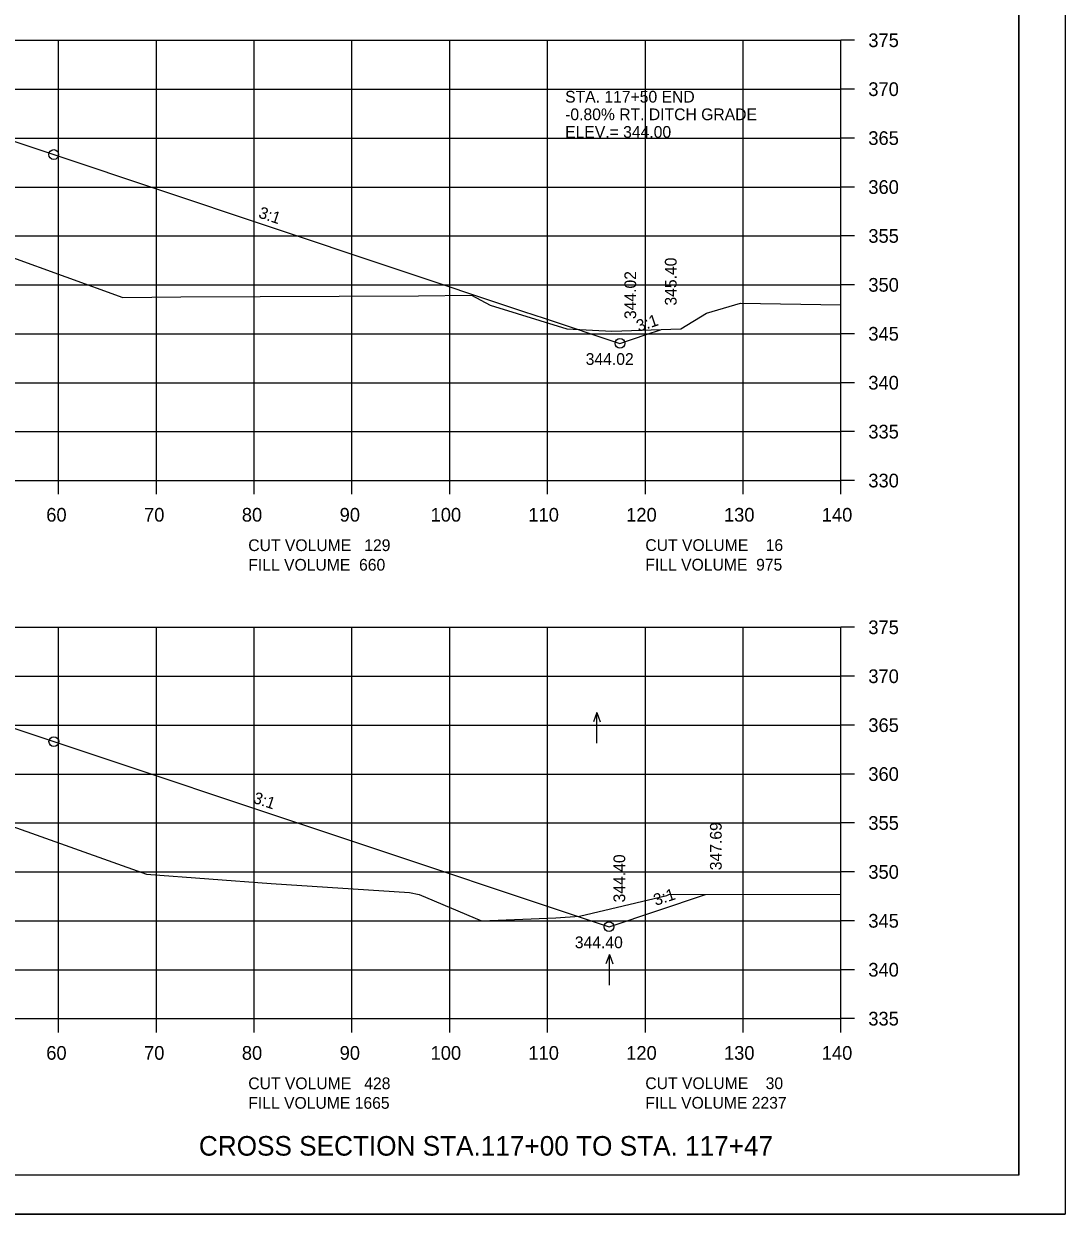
# Model space of a CAD drawing. Extents: x 1374859 to 1376773, y 382242 to 389804.
# Drawn here: x 1376191 to 1376297.5, y 383521.8 to 383643.4 of the extents above; entities that cross this region are included whole.
import ezdxf

# ---------------------------------------------------------------- set-up
doc = ezdxf.new("R2010")
doc.units = 0
for name, color, linetype in [('R_Axis', 7, 'Continuous'), ('R_Axis Annot', 7, 'Continuous'), ('R_Border', 7, 'Continuous'), ('R_Detour Annot', 7, 'Continuous'), ('R_Draft', 7, 'Continuous'), ('R_Exist Surface', 7, 'Continuous'), ('R_Fin Surface', 7, 'Continuous'), ('R_Grid', 7, 'Continuous'), ('R_No Plot', 7, 'Continuous'), ('R_Water Annot', 7, 'Continuous'), ('R_Xsect Elev', 7, 'Continuous'), ('R_Xsect Slope', 7, 'Continuous')]:
    doc.layers.add(name, color=color, linetype=linetype)

msp = doc.modelspace()

# ---------------------------------------------------------------- linework, layer by layer
at = {"layer": 'R_Axis'}
for p, q in [((1376274.57, 383596.75), (1376274.57, 383641.75)), ((1376275.97, 383641.75), (1376274.57, 383641.75)), ((1376275.97, 383636.75), (1376274.57, 383636.75)), ((1376275.97, 383631.75), (1376274.57, 383631.75)), ((1376275.97, 383626.75), (1376274.57, 383626.75)), ((1376275.97, 383621.75), (1376274.57, 383621.75)), ((1376275.97, 383616.75), (1376274.57, 383616.75)), ((1376275.97, 383611.75), (1376274.57, 383611.75)), ((1376275.97, 383606.75), (1376274.57, 383606.75)), ((1376275.97, 383601.75), (1376274.57, 383601.75)), ((1375994.57, 383596.75), (1376274.57, 383596.75)), ((1376194.57, 383595.35), (1376194.57, 383596.75)), ((1376204.57, 383595.35), (1376204.57, 383596.75)), ((1376214.57, 383595.35), (1376214.57, 383596.75)), ((1376224.57, 383595.35), (1376224.57, 383596.75)), ((1376234.57, 383595.35), (1376234.57, 383596.75)), ((1376244.57, 383595.35), (1376244.57, 383596.75)), ((1376254.57, 383595.35), (1376254.57, 383596.75)), ((1376264.57, 383595.35), (1376264.57, 383596.75)), ((1376274.57, 383595.35), (1376274.57, 383596.75)), ((1376275.97, 383596.75), (1376274.57, 383596.75)), ((1376274.57, 383541.75), (1376274.57, 383581.75)), ((1376275.97, 383581.75), (1376274.57, 383581.75)), ((1376275.97, 383576.75), (1376274.57, 383576.75)), ((1376275.97, 383571.75), (1376274.57, 383571.75)), ((1376275.97, 383566.75), (1376274.57, 383566.75)), ((1376275.97, 383561.75), (1376274.57, 383561.75)), ((1376275.97, 383556.75), (1376274.57, 383556.75)), ((1376275.97, 383551.75), (1376274.57, 383551.75)), ((1376275.97, 383546.75), (1376274.57, 383546.75)), ((1375994.57, 383541.75), (1376274.57, 383541.75)), ((1376194.57, 383540.35), (1376194.57, 383541.75)), ((1376204.57, 383540.35), (1376204.57, 383541.75)), ((1376214.57, 383540.35), (1376214.57, 383541.75)), ((1376224.57, 383540.35), (1376224.57, 383541.75)), ((1376234.57, 383540.35), (1376234.57, 383541.75)), ((1376244.57, 383540.35), (1376244.57, 383541.75)), ((1376254.57, 383540.35), (1376254.57, 383541.75)), ((1376264.57, 383540.35), (1376264.57, 383541.75)), ((1376274.57, 383540.35), (1376274.57, 383541.75)), ((1376275.97, 383541.75), (1376274.57, 383541.75))]:
    msp.add_line(p, q, dxfattribs=at)
at = {"layer": 'R_Border'}
for q in [(1376292.75, 383731.21), (1375976.57, 383525.75)]:
    msp.add_line((1376292.75, 383525.75), q, dxfattribs=at)
at = {"layer": 'R_Exist Surface'}
for points in [[(1376177.8, 383623.92), (1376201.15, 383615.47), (1376207.06, 383615.53), (1376231.38, 383615.64), (1376236.8, 383615.7), (1376238.7, 383614.67), (1376246.54, 383612.27), (1376251.16, 383612.03), (1376258.19, 383612.24), (1376260.84, 383613.84), (1376264.29, 383614.89), (1376274.57, 383614.72)], [(1376182.38, 383564.04), (1376203.57, 383556.51), (1376216.32, 383555.58), (1376230.46, 383554.66), (1376231.44, 383554.43), (1376237.83, 383551.76), (1376245.42, 383552.07), (1376247.84, 383552.23), (1376256.76, 383554.35), (1376256.98, 383554.43), (1376274.57, 383554.49)]]:
    msp.add_lwpolyline(points, dxfattribs=at)
at = {"layer": 'R_Fin Surface'}
for points in [[(1376021.3, 383605.53), (1376091.7, 383628.96), (1376098.93, 383629.52), (1376105.08, 383629.99), (1376127.64, 383631.73), (1376134.58, 383632.26), (1376157.14, 383634), (1376164.08, 383634.53), (1376167.2, 383634.77), (1376177.58, 383635.57), (1376183.84, 383633.48), (1376185.75, 383632.85), (1376192.14, 383630.72), (1376194.08, 383630.07), (1376215.8, 383622.83), (1376242.12, 383614.04), (1376244.24, 383613.34), (1376251.97, 383610.77), (1376254.66, 383611.67), (1376256.11, 383612.15)], [(1376005.04, 383556.78), (1376025.94, 383549.82), (1376075.09, 383566.2), (1376077.63, 383566.62), (1376091.59, 383568.95), (1376105.09, 383569.99), (1376134.59, 383572.26), (1376164.09, 383574.53), (1376177.59, 383575.57), (1376185.76, 383572.85), (1376194.09, 383570.07), (1376250.86, 383551.15), (1376260.73, 383554.44)]]:
    msp.add_lwpolyline(points, dxfattribs=at)
at = {"layer": 'R_Grid'}
for p, q in [((1375994.57, 383641.75), (1376274.57, 383641.75)), ((1376194.57, 383596.75), (1376194.57, 383641.75)), ((1376204.57, 383596.75), (1376204.57, 383641.75)), ((1376214.57, 383596.75), (1376214.57, 383641.75)), ((1376224.57, 383596.75), (1376224.57, 383641.75)), ((1376234.57, 383596.75), (1376234.57, 383641.75)), ((1376244.57, 383596.75), (1376244.57, 383641.75)), ((1376254.57, 383596.75), (1376254.57, 383641.75)), ((1376264.57, 383596.75), (1376264.57, 383641.75)), ((1376274.57, 383596.75), (1376274.57, 383641.75)), ((1375994.57, 383636.75), (1376274.57, 383636.75)), ((1375994.57, 383631.75), (1376274.57, 383631.75)), ((1375994.57, 383626.75), (1376274.57, 383626.75)), ((1375994.57, 383621.75), (1376274.57, 383621.75)), ((1375994.57, 383616.75), (1376274.57, 383616.75)), ((1375994.57, 383611.75), (1376274.57, 383611.75)), ((1375994.57, 383606.75), (1376274.57, 383606.75)), ((1375994.57, 383601.75), (1376274.57, 383601.75)), ((1375994.57, 383596.75), (1376274.57, 383596.75)), ((1375994.57, 383581.75), (1376274.57, 383581.75)), ((1376194.57, 383541.75), (1376194.57, 383581.75)), ((1376204.57, 383541.75), (1376204.57, 383581.75)), ((1376214.57, 383541.75), (1376214.57, 383581.75)), ((1376224.57, 383541.75), (1376224.57, 383581.75)), ((1376234.57, 383541.75), (1376234.57, 383581.75)), ((1376244.57, 383541.75), (1376244.57, 383581.75)), ((1376254.57, 383541.75), (1376254.57, 383581.75)), ((1376264.57, 383541.75), (1376264.57, 383581.75)), ((1376274.57, 383541.75), (1376274.57, 383581.75)), ((1375994.57, 383576.75), (1376274.57, 383576.75)), ((1375994.57, 383571.75), (1376274.57, 383571.75)), ((1375994.57, 383566.75), (1376274.57, 383566.75)), ((1375994.57, 383561.75), (1376274.57, 383561.75)), ((1375994.57, 383556.75), (1376274.57, 383556.75)), ((1375994.57, 383551.75), (1376274.57, 383551.75)), ((1375994.57, 383546.75), (1376274.57, 383546.75)), ((1375994.57, 383541.75), (1376274.57, 383541.75))]:
    msp.add_line(p, q, dxfattribs=at)
at = {"layer": 'R_No Plot'}
msp.add_line((1375964.17, 383521.77), (1376297.5, 383521.77), dxfattribs=at)
for points in [[(1375964.16, 383735.1), (1376297.5, 383735.1), (1376297.5, 383521.77), (1375964.16, 383521.77)], [(1376210.49, 383731.21), (1376210.49, 383721.33), (1376246.22, 383721.33), (1376246.22, 383718.41), (1376269.42, 383718.41), (1376269.42, 383694.08), (1376292.75, 383694.08), (1376292.75, 383525.75), (1375976.57, 383525.75), (1375976.57, 383731.21)]]:
    msp.add_lwpolyline(points, close=True, dxfattribs=at)
for centre in [(1376194.08, 383630.07), (1376251.97, 383610.77), (1376194.09, 383570.07), (1376250.86, 383551.15)]:
    msp.add_circle(centre, 0.5, dxfattribs=at)
at = {"layer": 'R_Water Annot'}
for p, q in [((1376249.61, 383573.05), (1376249.26, 383572.09)), ((1376249.61, 383569.91), (1376249.61, 383573.05)), ((1376249.61, 383573.05), (1376249.96, 383572.09)), ((1376250.89, 383548.3), (1376250.54, 383547.34)), ((1376250.89, 383545.16), (1376250.89, 383548.3)), ((1376250.89, 383548.3), (1376251.24, 383547.34))]:
    msp.add_line(p, q, dxfattribs=at)

# ---------------------------------------------------------------- texts
at = {"layer": 'R_Axis Annot'}
for s, height, p in [('375', 1.4, (1376277.37, 383641.05)), ('370', 1.4, (1376277.37, 383636.05)), ('365', 1.4, (1376277.37, 383631.05)), ('360', 1.4, (1376277.37, 383626.05)), ('355', 1.4, (1376277.37, 383621.05)), ('350', 1.4, (1376277.37, 383616.05)), ('345', 1.4, (1376277.37, 383611.05)), ('340', 1.4, (1376277.37, 383606.05)), ('335', 1.4, (1376277.37, 383601.05)), ('330', 1.4, (1376277.37, 383596.05)), ('60', 1.4, (1376193.31, 383592.55)), ('70', 1.4, (1376203.31, 383592.55)), ('80', 1.4, (1376213.31, 383592.55)), ('90', 1.4, (1376223.31, 383592.55)), ('100', 1.4, (1376232.61, 383592.55)), ('110', 1.4, (1376242.61, 383592.55)), ('120', 1.4, (1376252.61, 383592.55)), ('130', 1.4, (1376262.61, 383592.55)), ('140', 1.4, (1376272.61, 383592.55)), ('CUT VOLUME   129', 1.2, (1376213.97, 383589.54)), ('CUT VOLUME    16', 1.2, (1376254.57, 383589.55)), ('FILL VOLUME  660', 1.2, (1376213.97, 383587.54)), ('FILL VOLUME  975', 1.2, (1376254.57, 383587.55)), ('375', 1.4, (1376277.37, 383581.05)), ('370', 1.4, (1376277.37, 383576.05)), ('365', 1.4, (1376277.37, 383571.05)), ('360', 1.4, (1376277.37, 383566.05)), ('355', 1.4, (1376277.37, 383561.05)), ('350', 1.4, (1376277.37, 383556.05)), ('345', 1.4, (1376277.37, 383551.05)), ('340', 1.4, (1376277.37, 383546.05)), ('335', 1.4, (1376277.37, 383541.05)), ('60', 1.4, (1376193.31, 383537.55)), ('70', 1.4, (1376203.31, 383537.55)), ('80', 1.4, (1376213.31, 383537.55)), ('90', 1.4, (1376223.31, 383537.55)), ('100', 1.4, (1376232.61, 383537.55)), ('110', 1.4, (1376242.61, 383537.55)), ('120', 1.4, (1376252.61, 383537.55)), ('130', 1.4, (1376262.61, 383537.55)), ('140', 1.4, (1376272.61, 383537.55)), ('CUT VOLUME   428', 1.2, (1376213.97, 383534.54)), ('CUT VOLUME    30', 1.2, (1376254.57, 383534.55)), ('FILL VOLUME 1665', 1.2, (1376213.97, 383532.54)), ('FILL VOLUME 2237', 1.2, (1376254.57, 383532.55))]:
    msp.add_text(s, height=height, dxfattribs=at).set_placement(p)
at = {"layer": 'R_Detour Annot'}
for s, p in [('STA. 117+50 END', (1376246.37, 383635.38)), ('-0.80% RT. DITCH GRADE', (1376246.37, 383633.58)), ('ELEV.= 344.00', (1376246.37, 383631.78))]:
    msp.add_text(s, height=1.2, dxfattribs=at).set_placement(p)
at = {"layer": 'R_Draft'}
msp.add_text('CROSS SECTION STA.117+00 TO STA. 117+47', height=2, dxfattribs=at).set_placement((1376208.92, 383527.75))
at = {"layer": 'R_Xsect Elev'}
for s, p in [('345.40', (1376257.77, 383614.63)), ('344.02', (1376253.63, 383613.25)), ('347.69', (1376262.38, 383556.92)), ('344.40', (1376252.51, 383553.63))]:
    msp.add_text(s, height=1.2, rotation=90, dxfattribs=at).set_placement(p)
for s, p in [('344.02', (1376248.47, 383608.57)), ('344.40', (1376247.36, 383548.95))]:
    msp.add_text(s, height=1.2, dxfattribs=at).set_placement(p)
at = {"layer": 'R_Xsect Slope'}
for rotation, p in [(341.5654, (1376214.93, 383623.65)), (18.4344, (1376253.88, 383611.94)), (341.5654, (1376214.38, 383563.83)), (18.4349, (1376255.63, 383553.27))]:
    msp.add_text('3:1', height=1.2, rotation=rotation, dxfattribs=at).set_placement(p)

doc.saveas('drawing.dxf')
